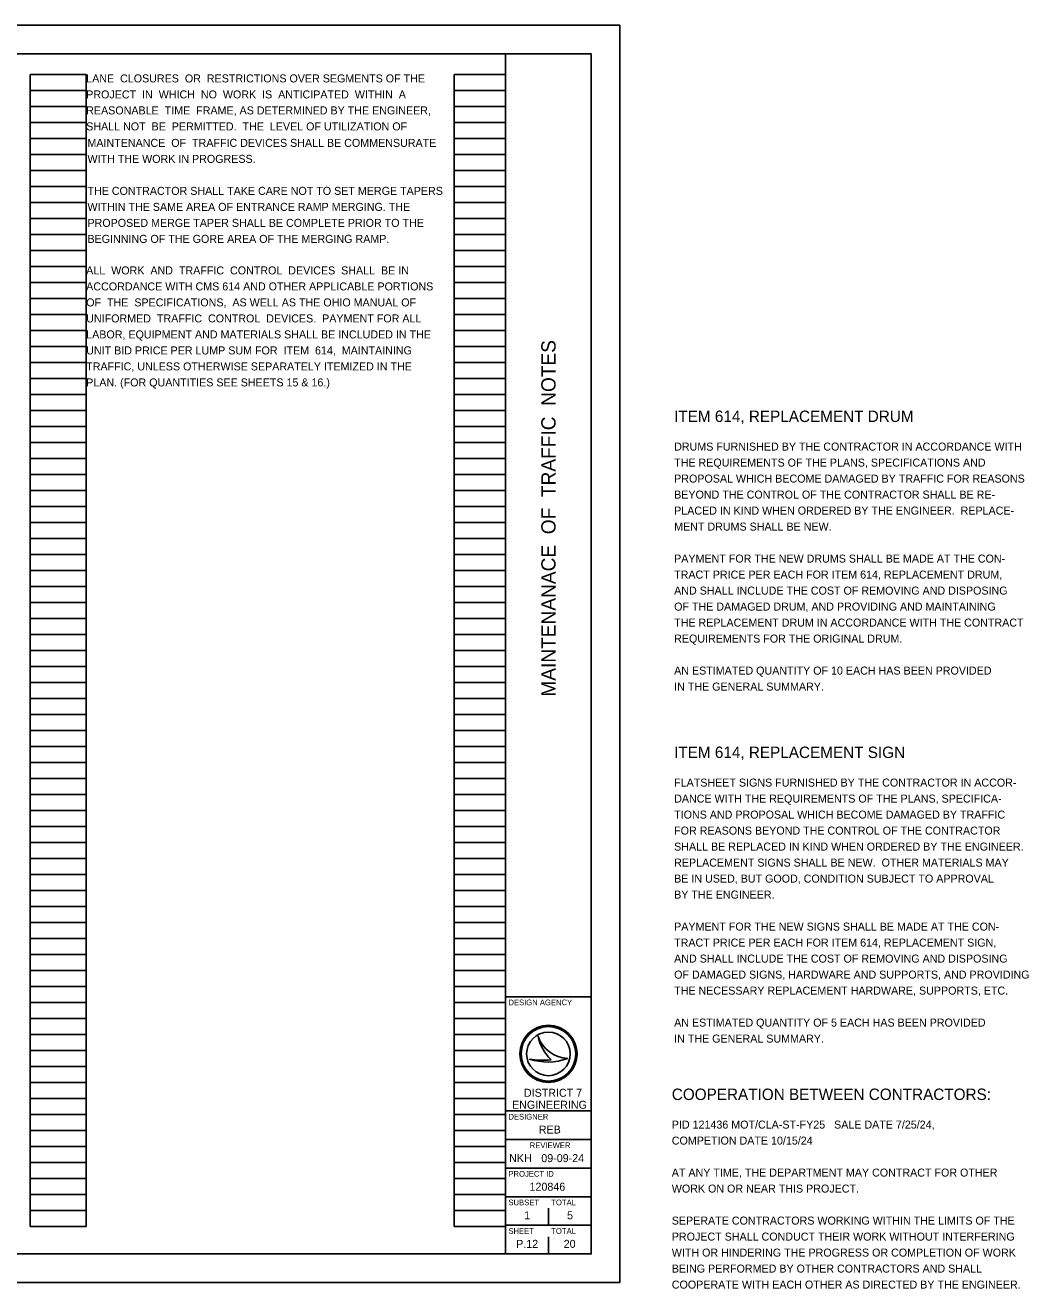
# Model space of a CAD drawing. Extents: x 0 to 41.2, y -0.1 to 22.
# Drawn here: x 23.59 to 41.16, y -0.11 to 22 of the extents above; entities that cross this region are included whole.
import ezdxf

# ---------------------------------------------------------------- set-up
doc = ezdxf.new("R2010")
doc.units = 0
for name, color, linetype in [('Default', 7, 'Continuous'), ('SH_Border', 7, 'Continuous'), ('SH_Cut_Line', 7, 'Continuous'), ('SH_Data', 7, 'Continuous'), ('SH_Text', 7, 'Continuous')]:
    doc.layers.add(name, color=color, linetype=linetype)

msp = doc.modelspace()

# ---------------------------------------------------------------- linework, layer by layer
at = {"layer": 'SH_Border'}
for p, q in [((32, 0.5), (32, 21.5)), ((32, 5), (33.5, 5)), ((32, 3), (33.5, 3)), ((32, 2.5), (33.5, 2.5)), ((32, 2), (33.5, 2)), ((32, 1.5), (33.5, 1.5)), ((32, 1), (33.5, 1))]:
    msp.add_line(p, q, dxfattribs=at)
msp.add_lwpolyline([(1.5, 21.5), (33.5, 21.5), (33.5, 0.5), (1.5, 0.5)], close=True, dxfattribs=at)
at = {"layer": 'SH_Cut_Line'}
msp.add_lwpolyline([(0, 0), (34, 0), (34, 22), (0, 22)], close=True, dxfattribs=at)
at = {"layer": 'SH_Data'}
for p, q in [((23.68, 0.98), (23.68, 21.14)), ((23.68, 21.14), (24.66, 21.14)), ((24.66, 0.98), (24.66, 21.14)), ((31.1, 0.98), (31.1, 21.14)), ((31.1, 21.14), (32, 21.14)), ((32, 0.98), (32, 21.14)), ((23.68, 20.86), (24.66, 20.86)), ((31.1, 20.86), (32, 20.86)), ((23.68, 20.58), (24.66, 20.58)), ((31.1, 20.58), (32, 20.58)), ((23.68, 20.3), (24.66, 20.3)), ((31.1, 20.3), (32, 20.3)), ((23.68, 20.02), (24.66, 20.02)), ((31.1, 20.02), (32, 20.02)), ((23.68, 19.74), (24.66, 19.74)), ((31.1, 19.74), (32, 19.74)), ((23.68, 19.46), (24.66, 19.46)), ((31.1, 19.46), (32, 19.46)), ((23.68, 19.18), (24.66, 19.18)), ((31.1, 19.18), (32, 19.18)), ((23.68, 18.9), (24.66, 18.9)), ((31.1, 18.9), (32, 18.9)), ((23.68, 18.62), (24.66, 18.62)), ((31.1, 18.62), (32, 18.62)), ((23.68, 18.34), (24.66, 18.34)), ((31.1, 18.34), (32, 18.34)), ((23.68, 18.06), (24.66, 18.06)), ((31.1, 18.06), (32, 18.06)), ((23.68, 17.78), (24.66, 17.78)), ((31.1, 17.78), (32, 17.78)), ((23.68, 17.5), (24.66, 17.5)), ((31.1, 17.5), (32, 17.5)), ((23.68, 17.22), (24.66, 17.22)), ((31.1, 17.22), (32, 17.22)), ((23.68, 16.94), (24.66, 16.94)), ((31.1, 16.94), (32, 16.94)), ((23.68, 16.66), (24.66, 16.66)), ((31.1, 16.66), (32, 16.66)), ((23.68, 16.38), (24.66, 16.38)), ((31.1, 16.38), (32, 16.38)), ((23.68, 16.1), (24.66, 16.1)), ((31.1, 16.1), (32, 16.1)), ((23.68, 15.82), (24.66, 15.82)), ((31.1, 15.82), (32, 15.82)), ((23.68, 15.54), (24.66, 15.54)), ((31.1, 15.54), (32, 15.54)), ((23.68, 15.26), (24.66, 15.26)), ((31.1, 15.26), (32, 15.26)), ((23.68, 14.98), (24.66, 14.98)), ((31.1, 14.98), (32, 14.98)), ((23.68, 14.7), (24.66, 14.7)), ((31.1, 14.7), (32, 14.7)), ((23.68, 14.42), (24.66, 14.42)), ((31.1, 14.42), (32, 14.42)), ((23.68, 14.14), (24.66, 14.14)), ((31.1, 14.14), (32, 14.14)), ((23.68, 13.86), (24.66, 13.86)), ((31.1, 13.86), (32, 13.86)), ((23.68, 13.58), (24.66, 13.58)), ((31.1, 13.58), (32, 13.58)), ((23.68, 13.3), (24.66, 13.3)), ((31.1, 13.3), (32, 13.3)), ((23.68, 13.02), (24.66, 13.02)), ((31.1, 13.02), (32, 13.02)), ((23.68, 12.74), (24.66, 12.74)), ((31.1, 12.74), (32, 12.74)), ((23.68, 12.46), (24.66, 12.46)), ((31.1, 12.46), (32, 12.46)), ((23.68, 12.18), (24.66, 12.18)), ((31.1, 12.18), (32, 12.18)), ((23.68, 11.9), (24.66, 11.9)), ((31.1, 11.9), (32, 11.9)), ((23.68, 11.62), (24.66, 11.62)), ((31.1, 11.62), (32, 11.62)), ((23.68, 11.34), (24.66, 11.34)), ((31.1, 11.34), (32, 11.34)), ((23.68, 11.06), (24.66, 11.06)), ((31.1, 11.06), (32, 11.06)), ((23.68, 10.78), (24.66, 10.78)), ((31.1, 10.78), (32, 10.78)), ((23.68, 10.5), (24.66, 10.5)), ((31.1, 10.5), (32, 10.5)), ((23.68, 10.22), (24.66, 10.22)), ((31.1, 10.22), (32, 10.22)), ((23.68, 9.94), (24.66, 9.94)), ((31.1, 9.94), (32, 9.94)), ((23.68, 9.66), (24.66, 9.66)), ((31.1, 9.66), (32, 9.66)), ((23.68, 9.38), (24.66, 9.38)), ((31.1, 9.38), (32, 9.38)), ((23.68, 9.1), (24.66, 9.1)), ((31.1, 9.1), (32, 9.1)), ((23.68, 8.82), (24.66, 8.82)), ((31.1, 8.82), (32, 8.82)), ((23.68, 8.54), (24.66, 8.54)), ((31.1, 8.54), (32, 8.54)), ((23.68, 8.26), (24.66, 8.26)), ((31.1, 8.26), (32, 8.26)), ((23.68, 7.98), (24.66, 7.98)), ((31.1, 7.98), (32, 7.98)), ((23.68, 7.7), (24.66, 7.7)), ((31.1, 7.7), (32, 7.7)), ((23.68, 7.42), (24.66, 7.42)), ((31.1, 7.42), (32, 7.42)), ((23.68, 7.14), (24.66, 7.14)), ((31.1, 7.14), (32, 7.14)), ((23.68, 6.86), (24.66, 6.86)), ((31.1, 6.86), (32, 6.86)), ((23.68, 6.58), (24.66, 6.58)), ((31.1, 6.58), (32, 6.58)), ((23.68, 6.3), (24.66, 6.3)), ((31.1, 6.3), (32, 6.3)), ((23.68, 6.02), (24.66, 6.02)), ((31.1, 6.02), (32, 6.02)), ((23.68, 5.74), (24.66, 5.74)), ((31.1, 5.74), (32, 5.74)), ((23.68, 5.46), (24.66, 5.46)), ((31.1, 5.46), (32, 5.46)), ((23.68, 5.18), (24.66, 5.18)), ((31.1, 5.18), (32, 5.18)), ((23.68, 4.9), (24.66, 4.9)), ((31.1, 4.9), (32, 4.9)), ((23.68, 4.62), (24.66, 4.62)), ((31.1, 4.62), (32, 4.62)), ((23.68, 4.34), (24.66, 4.34)), ((31.1, 4.34), (32, 4.34)), ((32.567, 4.31), (32.567, 4.31)), ((23.68, 4.06), (24.66, 4.06)), ((31.1, 4.06), (32, 4.06)), ((32.75, 4), (32.75, 4)), ((23.68, 3.78), (24.66, 3.78)), ((31.1, 3.78), (32, 3.78)), ((32.417, 3.91), (32.417, 3.91)), ((33.087, 3.919), (33.087, 3.919)), ((23.68, 3.5), (24.66, 3.5)), ((31.1, 3.5), (32, 3.5)), ((23.68, 3.22), (24.66, 3.22)), ((31.1, 3.22), (32, 3.22)), ((23.68, 2.94), (24.66, 2.94)), ((31.1, 2.94), (32, 2.94)), ((23.68, 2.66), (24.66, 2.66)), ((31.1, 2.66), (32, 2.66)), ((23.68, 2.38), (24.66, 2.38)), ((31.1, 2.38), (32, 2.38)), ((23.68, 2.1), (24.66, 2.1)), ((31.1, 2.1), (32, 2.1)), ((23.68, 1.82), (24.66, 1.82)), ((31.1, 1.82), (32, 1.82)), ((23.68, 1.54), (24.66, 1.54)), ((31.1, 1.54), (32, 1.54)), ((23.68, 1.26), (24.66, 1.26)), ((31.1, 1.26), (32, 1.26)), ((32.75, 1), (32.75, 1.3)), ((23.68, 0.98), (24.66, 0.98)), ((31.1, 0.98), (32, 0.98)), ((32.375, 0.675), (32.375, 0.675)), ((32.75, 0.5), (32.75, 0.8))]:
    msp.add_line(p, q, dxfattribs=at)
for radius in [0.5, 0.477, 0.477, 0.382]:
    msp.add_circle((32.75, 4), radius, dxfattribs=at)
for centre, radius, start, end in [((33.116, 4.498), 0.58, 198.9257, 198.9319), ((33.347, 4.47), 0.796, 191.6379, 191.6421), ((33.116, 4.498), 0.58, 198.9319, 267.1657), ((33.347, 4.47), 0.796, 191.6421, 226.0947), ((32.739, 4.87), 1.013, 251.4576, 290.0832), ((32.648, 5.154), 1.266, 259.4964, 259.4995), ((32.739, 4.87), 1.013, 251.4527, 251.4576), ((32.648, 5.154), 1.266, 259.4995, 276.6672)]:
    msp.add_arc(centre, radius, start, end, dxfattribs=at)

# ---------------------------------------------------------------- texts
at = {"layer": 'Default'}
for s, height, p in [('ITEM 614, REPLACEMENT DRUM', 0.2, (34.95, 15.057)), ('ITEM 614, REPLACEMENT SIGN', 0.2, (34.95, 9.177)), ('COOPERATION BETWEEN CONTRACTORS:', 0.2, (34.909, 3.192)), ('120846', 0.14, (32.419, 1.605))]:
    msp.add_text(s, height=height, dxfattribs=at).set_placement(p)
at = {"layer": 'SH_Data'}
msp.add_text('MAINTENANACE  OF  TRAFFIC  NOTES', height=0.25, rotation=90, dxfattribs=at).set_placement((32.875, 10.251))
for s, height, p in [('DESIGN AGENCY', 0.1, (32.05, 4.85)), ('DESIGNER', 0.1, (32.05, 2.85)), ('REB', 0.14, (32.581, 2.605)), ('REVIEWER', 0.1, (32.422, 2.35)), ('NKH', 0.14, (32.062, 2.105)), ('09-09-24', 0.14, (32.625, 2.105)), ('PROJECT ID', 0.1, (32.05, 1.85)), ('SUBSET', 0.1, (32.05, 1.35)), ('TOTAL', 0.1, (32.8, 1.35)), ('1', 0.14, (32.325, 1.105)), ('5', 0.14, (33.076, 1.105)), ('SHEET', 0.1, (32.05, 0.85)), ('TOTAL', 0.1, (32.8, 0.85)), ('P.12', 0.14, (32.185, 0.605)), ('20', 0.14, (33.017, 0.605))]:
    msp.add_text(s, height=height, dxfattribs=at).set_placement(p)
at = {"layer": 'SH_Text'}
for s, p in [('LANE  CLOSURES  OR  RESTRICTIONS OVER SEGMENTS OF THE', (24.66, 21)), ('PROJECT  IN  WHICH  NO  WORK  IS  ANTICIPATED  WITHIN  A', (24.66, 20.72)), ('REASONABLE  TIME  FRAME, AS DETERMINED BY THE ENGINEER,', (24.66, 20.44)), ('SHALL NOT  BE  PERMITTED.  THE  LEVEL OF UTILIZATION OF', (24.66, 20.16)), ('MAINTENANCE  OF  TRAFFIC DEVICES SHALL BE COMMENSURATE', (24.682, 19.872)), ('WITH THE WORK IN PROGRESS.', (24.682, 19.592)), ('THE CONTRACTOR SHALL TAKE CARE NOT TO SET MERGE TAPERS  ', (24.682, 19.032)), ('WITHIN THE SAME AREA OF ENTRANCE RAMP MERGING. THE ', (24.682, 18.752)), ('PROPOSED MERGE TAPER SHALL BE COMPLETE PRIOR TO THE ', (24.682, 18.472)), ('BEGINNING OF THE GORE AREA OF THE MERGING RAMP.', (24.682, 18.192)), ('ALL  WORK  AND  TRAFFIC  CONTROL  DEVICES  SHALL  BE IN', (24.66, 17.64)), ('ACCORDANCE WITH CMS 614 AND OTHER APPLICABLE PORTIONS', (24.66, 17.36)), ('OF  THE  SPECIFICATIONS,  AS WELL AS THE OHIO MANUAL OF', (24.66, 17.08)), ('UNIFORMED  TRAFFIC  CONTROL  DEVICES.  PAYMENT FOR ALL', (24.66, 16.8)), ('LABOR, EQUIPMENT AND MATERIALS SHALL BE INCLUDED IN THE', (24.66, 16.52)), ('UNIT BID PRICE PER LUMP SUM FOR  ITEM  614,  MAINTAINING', (24.66, 16.24)), ('TRAFFIC, UNLESS OTHERWISE SEPARATELY ITEMIZED IN THE ', (24.66, 15.96)), ('PLAN. (FOR QUANTITIES SEE SHEETS 15 & 16.)', (24.66, 15.68)), ('DRUMS FURNISHED BY THE CONTRACTOR IN ACCORDANCE WITH', (34.95, 14.557)), ('THE REQUIREMENTS OF THE PLANS, SPECIFICATIONS AND', (34.95, 14.277)), ('PROPOSAL WHICH BECOME DAMAGED BY TRAFFIC FOR REASONS', (34.95, 13.997)), ('BEYOND THE CONTROL OF THE CONTRACTOR SHALL BE RE-', (34.95, 13.717)), ('PLACED IN KIND WHEN ORDERED BY THE ENGINEER.  REPLACE-', (34.95, 13.437)), ('MENT DRUMS SHALL BE NEW.', (34.95, 13.157)), ('PAYMENT FOR THE NEW DRUMS SHALL BE MADE AT THE CON-', (34.95, 12.597)), ('TRACT PRICE PER EACH FOR ITEM 614, REPLACEMENT DRUM,', (34.95, 12.317)), ('AND SHALL INCLUDE THE COST OF REMOVING AND DISPOSING', (34.95, 12.037)), ('OF THE DAMAGED DRUM, AND PROVIDING AND MAINTAINING', (34.95, 11.757)), ('THE REPLACEMENT DRUM IN ACCORDANCE WITH THE CONTRACT', (34.95, 11.477)), ('REQUIREMENTS FOR THE ORIGINAL DRUM.', (34.95, 11.197)), ('AN ESTIMATED QUANTITY OF 10 EACH HAS BEEN PROVIDED', (34.95, 10.637)), ('IN THE GENERAL SUMMARY.', (34.95, 10.357)), ('FLATSHEET SIGNS FURNISHED BY THE CONTRACTOR IN ACCOR-', (34.95, 8.677)), ('DANCE WITH THE REQUIREMENTS OF THE PLANS, SPECIFICA-', (34.95, 8.397)), ('TIONS AND PROPOSAL WHICH BECOME DAMAGED BY TRAFFIC', (34.95, 8.117)), ('FOR REASONS BEYOND THE CONTROL OF THE CONTRACTOR', (34.95, 7.837)), ('SHALL BE REPLACED IN KIND WHEN ORDERED BY THE ENGINEER.', (34.95, 7.557)), ('REPLACEMENT SIGNS SHALL BE NEW.  OTHER MATERIALS MAY', (34.95, 7.277)), ('BE IN USED, BUT GOOD, CONDITION SUBJECT TO APPROVAL', (34.95, 6.997)), ('BY THE ENGINEER.', (34.95, 6.717)), ('PAYMENT FOR THE NEW SIGNS SHALL BE MADE AT THE CON-', (34.95, 6.157)), ('TRACT PRICE PER EACH FOR ITEM 614, REPLACEMENT SIGN,', (34.95, 5.877)), ('AND SHALL INCLUDE THE COST OF REMOVING AND DISPOSING', (34.95, 5.597)), ('OF DAMAGED SIGNS, HARDWARE AND SUPPORTS, AND PROVIDING', (34.95, 5.317)), ('THE NECESSARY REPLACEMENT HARDWARE, SUPPORTS, ETC.', (34.95, 5.037)), ('AN ESTIMATED QUANTITY OF 5 EACH HAS BEEN PROVIDED', (34.95, 4.477)), ('IN THE GENERAL SUMMARY.', (34.95, 4.197)), ('    DISTRICT 7 ', (32.113, 3.249)), ('ENGINEERING', (32.113, 3.039)), ('PID 121436 MOT/CLA-ST-FY25   SALE DATE 7/25/24, ', (34.909, 2.692)), ('COMPETION DATE 10/15/24', (34.909, 2.412)), ('AT ANY TIME, THE DEPARTMENT MAY CONTRACT FOR OTHER ', (34.909, 1.852)), ('WORK ON OR NEAR THIS PROJECT.', (34.909, 1.572)), ('SEPERATE CONTRACTORS WORKING WITHIN THE LIMITS OF THE ', (34.909, 1.012)), ('PROJECT SHALL CONDUCT THEIR WORK WITHOUT INTERFERING ', (34.909, 0.732)), ('WITH OR HINDERING THE PROGRESS OR COMPLETION OF WORK', (34.909, 0.452)), ('BEING PERFORMED BY OTHER CONTRACTORS AND SHALL ', (34.909, 0.172)), ('COOPERATE WITH EACH OTHER AS DIRECTED BY THE ENGINEER.', (34.909, -0.108))]:
    msp.add_text(s, height=0.14, dxfattribs=at).set_placement(p)

doc.saveas('drawing.dxf')
